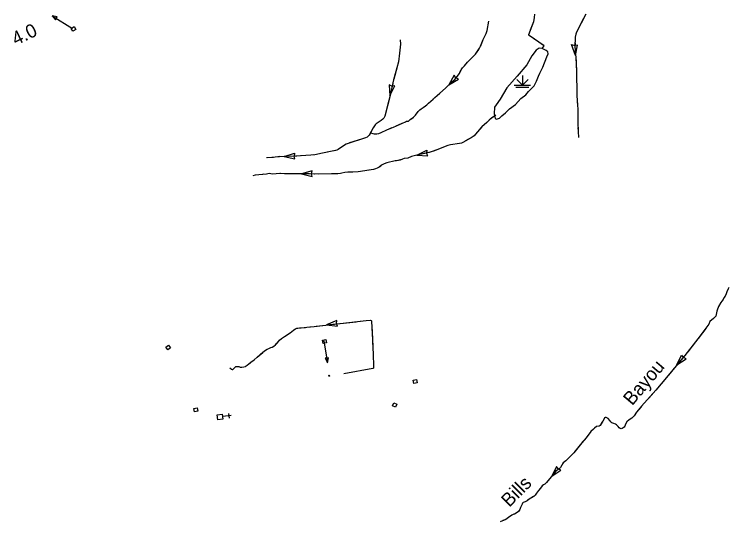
# Model space of a CAD drawing. Extents: x -160 to 6143532, y -375 to 762199.
# Drawn here: x -71.97 to -25.92, y -271.48 to -238.77 of the extents above; entities that cross this region are included whole.
import ezdxf

# ---------------------------------------------------------------- set-up
doc = ezdxf.new("R2010")
doc.units = 0
for name, color, linetype in [('Level 43', 7, 'Continuous'), ('Level 44', 7, 'Continuous'), ('Level 47', 7, 'Continuous'), ('Level 48', 7, 'Continuous'), ('Level 56', 7, 'Continuous'), ('Level 57', 7, 'Continuous')]:
    doc.layers.add(name, color=color, linetype=linetype)

msp = doc.modelspace()

# ---------------------------------------------------------------- linework, layer by layer
at = {"layer": 'Level 43'}
for p, q in [((-36.05, -240.727), (-35.835, -240.795)), ((-35.784, -241.429), (-36.05, -240.727)), ((-35.675, -240.76), (-35.832, -240.795)), ((-35.784, -241.429), (-35.675, -240.76)), ((-43.609, -242.702), (-43.952, -243.323)), ((-43.952, -243.323), (-43.344, -242.957)), ((-43.511, -242.864), (-43.609, -242.702)), ((-43.344, -242.957), (-43.509, -242.865)), ((-47.636, -243.399), (-47.806, -243.317)), ((-47.806, -243.317), (-47.756, -244.025)), ((-47.756, -244.025), (-47.445, -243.386)), ((-47.445, -243.386), (-47.634, -243.4)), ((-54.575, -247.94), (-53.897, -247.732)), ((-53.897, -247.732), (-53.939, -247.916)), ((-46.017, -247.853), (-45.386, -247.529)), ((-45.386, -247.529), (-45.395, -247.717)), ((-45.308, -247.888), (-45.394, -247.72)), ((-54.575, -247.94), (-53.883, -248.099)), ((-53.883, -248.099), (-53.939, -247.919)), ((-46.017, -247.853), (-45.308, -247.888)), ((-52.767, -248.871), (-53.453, -249.056)), ((-53.453, -249.056), (-52.767, -249.239)), ((-52.816, -249.054), (-52.767, -248.871)), ((-52.767, -249.239), (-52.816, -249.056)), ((-51.187, -258.52), (-51.839, -258.802)), ((-51.839, -258.802), (-51.134, -258.884)), ((-51.209, -258.708), (-51.187, -258.52)), ((-51.134, -258.884), (-51.209, -258.711)), ((-29.253, -261.381), (-28.952, -260.738)), ((-29.253, -261.381), (-28.671, -260.975)), ((-28.952, -260.738), (-28.844, -260.893)), ((-28.671, -260.975), (-28.842, -260.895)), ((-37.02, -267.917), (-37.331, -268.555)), ((-36.914, -268.073), (-37.02, -267.917)), ((-37.331, -268.555), (-36.742, -268.158)), ((-36.742, -268.158), (-36.912, -268.075))]:
    msp.add_line(p, q, dxfattribs=at)
for points in [[(-37.939, -240.971), (-37.82, -240.804), (-38.774, -240.144), (-38.8, -240.119), (-38.805, -240.068), (-38.475, -239.235), (-38.429, -238.975), (-38.41, -238.772)], [(-38.686, -239.768), (-38.475, -239.235), (-38.432, -238.993)], [(-35.137, -238.772), (-35.74, -239.924), (-35.782, -240.052), (-35.809, -240.246), (-35.837, -240.86), (-35.821, -241.058), (-35.767, -241.596), (-35.732, -242.365), (-35.705, -244.004), (-35.654, -244.905), (-35.65, -245.732), (-35.627, -246.319), (-35.608, -246.705)], [(-35.137, -238.772), (-35.43, -239.333)], [(-49.008, -246.404), (-48.867, -246.467), (-48.778, -246.488), (-48.689, -246.488), (-48.591, -246.484), (-48.481, -246.462), (-48.328, -246.403), (-47.949, -246.228), (-47.524, -246.046), (-46.742, -245.701), (-46.678, -245.671), (-46.568, -245.654), (-46.445, -245.561), (-46.236, -245.403), (-46.109, -245.272), (-45.93, -245.038), (-45.879, -244.974), (-45.828, -244.923), (-45.752, -244.859), (-45.539, -244.732), (-45.378, -244.608), (-45.272, -244.506), (-44.978, -244.238), (-44.864, -244.136), (-44.715, -244.009), (-44.536, -243.864), (-44.167, -243.537), (-43.997, -243.371), (-43.839, -243.201), (-43.763, -243.128), (-43.563, -242.971), (-43.478, -242.873), (-43.282, -242.584), (-43.163, -242.346), (-43.07, -242.214), (-42.959, -242.103), (-42.747, -241.861), (-42.534, -241.64), (-42.25, -241.342), (-41.978, -240.96), (-41.914, -240.836), (-41.744, -240.394), (-41.633, -240.19), (-41.544, -240.003), (-41.493, -239.824), (-41.383, -239.208)], [(-35.557, -239.575), (-35.74, -239.924), (-35.782, -240.052), (-35.809, -240.246), (-35.814, -240.34)], [(-41.9, -240.801), (-41.744, -240.394), (-41.633, -240.19), (-41.568, -240.053)], [(-38.213, -240.533), (-38.774, -240.144), (-38.8, -240.119), (-38.805, -240.068), (-38.787, -240.022)], [(-47.099, -240.414), (-47.082, -240.704), (-47.141, -241.273), (-47.209, -241.843), (-47.524, -242.991), (-47.77, -244.089), (-48.085, -245.339), (-48.147, -245.477), (-48.206, -245.537), (-48.329, -245.617), (-48.644, -245.834), (-48.699, -245.894), (-48.839, -246.089), (-49.094, -246.566), (-49.154, -246.625), (-49.226, -246.685), (-49.337, -246.731), (-50.446, -247.093), (-50.573, -247.148), (-50.684, -247.208), (-51.084, -247.493), (-51.173, -247.539), (-51.258, -247.556), (-52.104, -247.727), (-52.601, -247.829), (-52.864, -247.858), (-53.838, -247.914), (-54.896, -247.952), (-54.985, -247.956), (-55.16, -247.994), (-55.359, -248.007), (-55.716, -248.032)], [(-37.939, -240.971), (-37.82, -240.804), (-37.988, -240.688)], [(-35.826, -240.613), (-35.837, -240.86), (-35.821, -241.058), (-35.784, -241.429)], [(-47.123, -241.094), (-47.141, -241.273), (-47.209, -241.843), (-47.227, -241.906)], [(-42.558, -241.664), (-42.534, -241.64), (-42.25, -241.342), (-42.033, -241.038)], [(-35.762, -241.701), (-35.743, -242.11)], [(-47.299, -242.17), (-47.515, -242.96)], [(-43.243, -242.506), (-43.163, -242.346), (-43.07, -242.214), (-42.959, -242.103), (-42.747, -241.861)], [(-35.743, -242.11), (-35.732, -242.365), (-35.729, -242.52)], [(-43.952, -243.323), (-43.839, -243.201), (-43.763, -243.128), (-43.655, -243.043)], [(-43.655, -243.043), (-43.563, -242.971), (-43.478, -242.873), (-43.386, -242.738)], [(-35.725, -242.793), (-35.711, -243.612)], [(-47.576, -243.226), (-47.756, -244.025)], [(-44.765, -244.052), (-44.715, -244.009), (-44.536, -243.864), (-44.167, -243.537), (-44.145, -243.516)], [(-35.707, -243.885), (-35.705, -244.004), (-35.666, -244.703)], [(-47.821, -244.29), (-48.021, -245.084)], [(-45.592, -244.763), (-45.539, -244.732), (-45.378, -244.608), (-45.272, -244.506), (-44.978, -244.238), (-44.97, -244.231)], [(-46.375, -245.508), (-46.236, -245.403), (-46.109, -245.272), (-45.93, -245.038), (-45.879, -244.974), (-45.828, -244.923), (-45.818, -244.914)], [(-35.654, -244.975), (-35.65, -245.732), (-35.648, -245.794)], [(-40.932, -245.273), (-41.217, -245.471), (-41.364, -245.6), (-41.506, -245.744), (-41.843, -246.025), (-42.241, -246.493), (-42.332, -246.608), (-42.466, -246.699), (-43.017, -247.007), (-43.153, -247.074), (-43.282, -247.111), (-43.854, -247.192), (-44.014, -247.234), (-44.303, -247.331), (-44.664, -247.494), (-45.172, -247.67), (-46.1, -247.871), (-46.365, -247.951), (-46.605, -248.045), (-46.84, -248.072), (-46.945, -248.109), (-47.092, -248.171), (-47.199, -248.195), (-47.426, -248.221), (-47.589, -248.256), (-47.776, -248.299), (-47.961, -248.339), (-48.135, -248.411), (-48.29, -248.508), (-48.45, -248.633), (-48.589, -248.703), (-48.693, -248.732), (-48.819, -248.781), (-49.247, -248.853), (-49.795, -248.93), (-50.14, -248.954), (-50.341, -248.946), (-50.442, -248.946), (-50.659, -248.97), (-50.862, -249.013), (-50.945, -249.045), (-51.111, -249.048), (-51.506, -249.061), (-52.592, -249.078), (-52.937, -249.048), (-53.948, -249.064), (-54.381, -249.056), (-54.849, -249.043), (-55.322, -249.069), (-55.44, -249.048), (-55.528, -249.043), (-55.72, -249.075), (-55.977, -249.096), (-56.448, -249.142), (-56.598, -249.18)], [(-48.089, -245.349), (-48.147, -245.477), (-48.206, -245.537), (-48.329, -245.617), (-48.644, -245.834), (-48.688, -245.882)], [(-41.044, -245.351), (-41.217, -245.471), (-41.264, -245.512), (-41.462, -245.699)], [(-47.354, -245.97), (-46.972, -245.802)], [(-41.462, -245.699), (-41.506, -245.744), (-41.843, -246.025), (-42.049, -246.267)], [(-48.847, -246.103), (-49.04, -246.464)], [(-48.352, -246.412), (-48.328, -246.403), (-47.949, -246.228), (-47.604, -246.08)], [(-35.637, -246.067), (-35.627, -246.319), (-35.608, -246.705)], [(-49.593, -246.815), (-50.372, -247.069)], [(-49.04, -246.464), (-49.094, -246.566), (-49.154, -246.625), (-49.226, -246.685), (-49.334, -246.73)], [(-49.008, -246.404), (-48.867, -246.467), (-48.778, -246.488), (-48.689, -246.488), (-48.614, -246.485)], [(-42.226, -246.475), (-42.241, -246.493), (-42.332, -246.608), (-42.466, -246.699), (-42.891, -246.937)], [(-50.623, -247.175), (-50.684, -247.208), (-51.084, -247.493), (-51.173, -247.539), (-51.258, -247.556), (-51.328, -247.571)], [(-43.133, -247.064), (-43.153, -247.074), (-43.282, -247.111), (-43.854, -247.192), (-43.936, -247.213)], [(-51.596, -247.624), (-52.104, -247.727), (-52.399, -247.787)], [(-45.216, -247.68), (-46.017, -247.853)], [(-44.196, -247.295), (-44.303, -247.331), (-44.664, -247.494), (-44.957, -247.596)], [(-55.253, -248), (-55.359, -248.007), (-55.662, -248.028)], [(-54.848, -247.95), (-54.896, -247.952), (-54.985, -247.956), (-55.16, -247.994), (-55.253, -248)], [(-53.757, -247.909), (-53.838, -247.914), (-54.575, -247.94)], [(-52.667, -247.836), (-52.864, -247.858), (-53.484, -247.894)], [(-46.992, -248.127), (-47.327, -248.21), (-47.426, -248.221), (-47.589, -248.256), (-47.776, -248.299), (-47.961, -248.339), (-48.119, -248.405)], [(-48.348, -248.553), (-48.45, -248.633), (-48.589, -248.703), (-48.693, -248.732), (-48.819, -248.781), (-49.106, -248.829)], [(-55.904, -249.09), (-55.977, -249.096), (-56.448, -249.142), (-56.598, -249.18)], [(-54.818, -249.044), (-54.849, -249.043), (-55.322, -249.069), (-55.44, -249.048), (-55.528, -249.043), (-55.632, -249.06)], [(-53.726, -249.061), (-53.948, -249.064), (-54.381, -249.056), (-54.545, -249.051)], [(-53.043, -249.05), (-53.453, -249.056)], [(-52.635, -249.074), (-52.937, -249.048), (-53.043, -249.05)], [(-51.543, -249.062), (-52.362, -249.074)], [(-50.463, -248.949), (-50.659, -248.97), (-50.862, -249.013), (-50.945, -249.045), (-51.111, -249.048), (-51.27, -249.053)], [(-49.376, -248.871), (-49.795, -248.93), (-50.14, -248.954), (-50.19, -248.952)], [(-25.919, -256.392), (-25.949, -256.465), (-26.034, -256.657), (-26.084, -256.796), (-26.155, -256.941), (-26.24, -257.055), (-26.279, -257.165), (-26.361, -257.261), (-26.425, -257.353), (-26.57, -257.616), (-26.684, -257.914), (-26.726, -258.127), (-26.758, -258.237), (-26.907, -258.394), (-27.131, -258.578), (-27.195, -258.749), (-27.262, -258.834), (-27.901, -259.704), (-28.739, -260.769), (-30.268, -262.591), (-30.616, -263.003), (-31.543, -264.043), (-31.855, -264.423), (-32.018, -264.665), (-32.167, -264.803), (-32.331, -264.917), (-32.49, -265.055), (-32.568, -265.194), (-32.614, -265.322), (-32.654, -265.389), (-32.721, -265.443), (-32.788, -265.478), (-32.849, -265.492), (-32.913, -265.474), (-32.973, -265.425), (-33.048, -265.347), (-33.143, -265.24), (-33.218, -265.187), (-33.328, -265.158), (-33.452, -265.105), (-33.523, -265.045), (-33.587, -264.96), (-33.697, -264.839), (-33.772, -264.778), (-33.821, -264.771), (-33.874, -264.771), (-33.917, -264.793), (-33.956, -264.849), (-34.041, -264.995), (-34.151, -265.176), (-34.212, -265.29), (-34.272, -265.332), (-34.435, -265.35), (-34.567, -265.457), (-34.804, -265.659), (-35.11, -266.071), (-35.397, -266.391), (-35.912, -267.04), (-36.423, -267.566), (-36.583, -267.697), (-36.671, -267.836), (-36.753, -267.989), (-36.849, -268.077), (-37.065, -268.23), (-37.264, -268.472), (-37.658, -268.965), (-37.761, -269.054), (-37.864, -269.114), (-37.942, -269.178), (-38.048, -269.313), (-38.176, -269.462), (-38.318, -269.647), (-38.403, -269.771), (-38.489, -269.86), (-38.677, -269.963), (-38.787, -270.03), (-38.911, -270.13), (-39.032, -270.204), (-39.113, -270.222), (-39.177, -270.254)], [(-25.919, -256.392), (-25.949, -256.465), (-26.001, -256.582)], [(-26.001, -256.582), (-26.034, -256.657), (-26.084, -256.796), (-26.155, -256.941), (-26.166, -256.956)], [(-26.3, -257.19), (-26.361, -257.261), (-26.425, -257.353), (-26.57, -257.616), (-26.636, -257.79)], [(-58.083, -261.563), (-57.962, -261.657), (-57.933, -261.678), (-57.915, -261.682), (-57.892, -261.676), (-57.853, -261.649), (-57.772, -261.574), (-57.731, -261.514), (-57.69, -261.483), (-57.641, -261.473), (-57.578, -261.468), (-57.506, -261.48), (-57.417, -261.519), (-57.36, -261.53), (-57.297, -261.527), (-57.167, -261.499), (-57.069, -261.469), (-57.021, -261.444), (-56.956, -261.398), (-56.861, -261.301), (-56.717, -261.199), (-56.497, -261.038), (-56.321, -260.873), (-55.945, -260.565), (-55.775, -260.432), (-55.673, -260.368), (-55.562, -260.317), (-55.423, -260.263), (-55.344, -260.223), (-55.245, -260.169), (-55.137, -260.084), (-55.03, -259.966), (-54.94, -259.857), (-54.865, -259.775), (-54.743, -259.676), (-54.555, -259.555), (-54.111, -259.245), (-53.946, -259.116), (-53.84, -259.046), (-53.759, -259.013), (-53.689, -258.997), (-53.59, -258.982), (-53.47, -258.978), (-53.115, -258.948), (-52.636, -258.891), (-49.287, -258.517), (-49.009, -258.5), (-48.973, -258.509), (-48.944, -258.53), (-48.937, -258.558), (-48.869, -260.178), (-48.811, -261.378), (-48.808, -261.5), (-48.808, -261.558), (-48.824, -261.592), (-48.863, -261.614), (-50.725, -261.946)], [(-51.839, -258.802), (-51.025, -258.711)], [(-50.754, -258.68), (-49.94, -258.59)], [(-49.668, -258.559), (-49.287, -258.517), (-49.009, -258.5), (-48.973, -258.509), (-48.944, -258.53), (-48.937, -258.558), (-48.934, -258.613)], [(-53.975, -259.139), (-53.946, -259.116), (-53.84, -259.046), (-53.759, -259.013), (-53.689, -258.997), (-53.59, -258.982), (-53.47, -258.978), (-53.196, -258.955)], [(-52.924, -258.925), (-52.636, -258.891), (-52.518, -258.877)], [(-52.518, -258.877), (-52.111, -258.832)], [(-48.923, -258.886), (-48.889, -259.704)], [(-27.399, -259.02), (-27.883, -259.68)], [(-54.863, -259.774), (-54.743, -259.676), (-54.555, -259.555), (-54.194, -259.303)], [(-55.731, -260.404), (-55.673, -260.368), (-55.562, -260.317), (-55.423, -260.263), (-55.344, -260.223), (-55.245, -260.169), (-55.137, -260.084), (-55.042, -259.98)], [(-48.878, -259.977), (-48.869, -260.178), (-48.84, -260.795)], [(-28.051, -259.895), (-28.558, -260.539)], [(-56.575, -261.095), (-56.497, -261.038), (-56.321, -260.873), (-55.949, -260.568)], [(-28.726, -260.754), (-28.739, -260.769), (-29.253, -261.381)], [(-57.523, -261.477), (-57.506, -261.48), (-57.417, -261.519), (-57.36, -261.53), (-57.297, -261.527), (-57.167, -261.499), (-57.069, -261.469), (-57.021, -261.444), (-56.956, -261.398), (-56.861, -261.301), (-56.796, -261.255)], [(-29.692, -261.904), (-29.955, -262.218)], [(-29.428, -261.591), (-29.692, -261.904)], [(-30.131, -262.427), (-30.268, -262.591), (-30.616, -263.003), (-30.66, -263.052)], [(-30.842, -263.256), (-31.386, -263.868)], [(-31.567, -264.073), (-31.855, -264.423), (-32.018, -264.665), (-32.072, -264.715)], [(-33.894, -264.781), (-33.917, -264.793), (-33.956, -264.849), (-34.041, -264.995), (-34.117, -265.12)], [(-34.117, -265.12), (-34.151, -265.176), (-34.212, -265.29), (-34.272, -265.332), (-34.412, -265.348)], [(-33.031, -265.364), (-33.048, -265.347), (-33.143, -265.24), (-33.218, -265.187), (-33.328, -265.158), (-33.452, -265.105), (-33.523, -265.045), (-33.587, -264.96), (-33.662, -264.877)], [(-32.285, -264.885), (-32.331, -264.917), (-32.49, -265.055), (-32.568, -265.194), (-32.614, -265.322), (-32.654, -265.389), (-32.721, -265.443), (-32.788, -265.478), (-32.805, -265.482)], [(-34.628, -265.509), (-34.804, -265.659), (-35.11, -266.071), (-35.16, -266.127)], [(-35.342, -266.33), (-35.397, -266.391), (-35.855, -266.969)], [(-36.038, -267.171), (-36.423, -267.566), (-36.583, -267.697), (-36.615, -267.748)], [(-36.751, -267.985), (-36.753, -267.989), (-36.849, -268.077), (-37.065, -268.23), (-37.264, -268.472), (-37.331, -268.555)], [(-37.501, -268.768), (-37.658, -268.965), (-37.761, -269.054), (-37.864, -269.114), (-37.942, -269.178), (-38.048, -269.313), (-38.074, -269.343)], [(-38.247, -269.554), (-38.318, -269.647), (-38.403, -269.771), (-38.489, -269.86), (-38.505, -269.869)], [(-39.177, -270.254), (-39.22, -270.293), (-39.234, -270.35), (-39.255, -270.4), (-39.337, -270.563), (-39.39, -270.702), (-39.479, -270.823), (-39.612, -270.931), (-39.73, -270.995), (-39.816, -271.026), (-39.892, -271.052), (-40.108, -271.208), (-40.296, -271.332), (-40.655, -271.484)], [(-39.087, -270.217), (-39.113, -270.222), (-39.177, -270.254), (-39.22, -270.293), (-39.234, -270.35), (-39.255, -270.4), (-39.337, -270.563), (-39.39, -270.702), (-39.479, -270.823), (-39.533, -270.866)], [(-38.505, -269.869), (-38.677, -269.963), (-38.787, -270.03), (-38.853, -270.084)], [(-39.765, -271.007), (-39.816, -271.026), (-39.892, -271.052), (-40.108, -271.208), (-40.296, -271.332), (-40.473, -271.407)]]:
    msp.add_lwpolyline(points, dxfattribs=at)
at = {"layer": 'Level 44'}
for p, q in [((-39.221, -243.338), (-39.587, -242.972)), ((-39.221, -242.717), (-39.221, -243.338)), ((-39.221, -243.338), (-38.855, -242.972)), ((-39.738, -243.338), (-38.704, -243.338)), ((-39.635, -243.479), (-38.807, -243.479))]:
    msp.add_line(p, q, dxfattribs=at)
at = {"layer": 'Level 47'}
msp.add_lwpolyline([(-38.09, -242.559), (-37.911, -242.184), (-37.645, -241.509), (-37.553, -241.316), (-37.584, -241.195), (-37.695, -241.113), (-37.939, -240.971), (-38.132, -240.961), (-38.335, -241.093), (-38.609, -241.459), (-38.934, -242.028), (-39.554, -242.759), (-40.214, -243.511), (-40.651, -244.243), (-40.915, -244.619), (-41.017, -244.77), (-41.031, -245.194), (-40.973, -245.48), (-40.877, -245.527), (-40.75, -245.495), (-40.694, -245.469), (-40.546, -245.322), (-40.303, -245.115), (-40.043, -244.871), (-39.652, -244.578), (-39.311, -244.203), (-39.001, -243.975), (-38.822, -243.747), (-38.464, -243.389), (-38.302, -243.08), (-38.177, -242.758), (-38.09, -242.559)], dxfattribs=at)
at = {"layer": 'Level 56'}
for points in [[(-69.532, -238.865), (-68.21, -239.68)], [(-51.785, -261.145), (-51.988, -259.825)]]:
    msp.add_lwpolyline(points, dxfattribs=at)
for points in [[(-69.318, -239.121), (-69.207, -238.942), (-69.532, -238.865)], [(-68.187, -239.866), (-68.297, -239.681), (-68.112, -239.57), (-68.001, -239.755)], [(-62.033, -260.099), (-61.899, -260.267), (-62.067, -260.402), (-62.202, -260.234)], [(-51.888, -259.742), (-51.85, -259.954), (-52.062, -259.992), (-52.1, -259.78)], [(-51.716, -260.918), (-51.925, -260.95), (-51.772, -261.247)], [(-46.217, -262.572), (-46.253, -262.36), (-46.04, -262.324), (-46.004, -262.536)], [(-47.311, -263.903), (-47.397, -264.101), (-47.595, -264.014), (-47.509, -263.817)], [(-60.186, -264.146), (-60.148, -264.358), (-60.361, -264.396), (-60.398, -264.184)]]:
    msp.add_lwpolyline(points, close=True, dxfattribs=at)
msp.add_circle((-51.671, -262.072), 0.031, dxfattribs=at)
at = {"layer": 'Level 57'}
for p, q in [((-57.989, -264.64), (-58.542, -264.711)), ((-58.163, -264.506), (-58.124, -264.814))]:
    msp.add_line(p, q, dxfattribs=at)
msp.add_lwpolyline([(-58.883, -264.585), (-58.563, -264.544), (-58.521, -264.876), (-58.841, -264.917)], close=True, dxfattribs=at)

# ---------------------------------------------------------------- texts
at = {"layer": 'Level 43'}
for s, rotation, p in [('Bayou', 49.6432, (-32.141, -264.045)), ('Bills', 45.23, (-40.062, -270.597))]:
    msp.add_text(s, height=0.8737, rotation=rotation, dxfattribs=at).set_placement(p)
at = {"layer": 'Level 48'}
msp.add_text('4.0', height=0.8737, rotation=25.6182, dxfattribs=at).set_placement((-71.871, -240.804))

doc.saveas('drawing.dxf')
